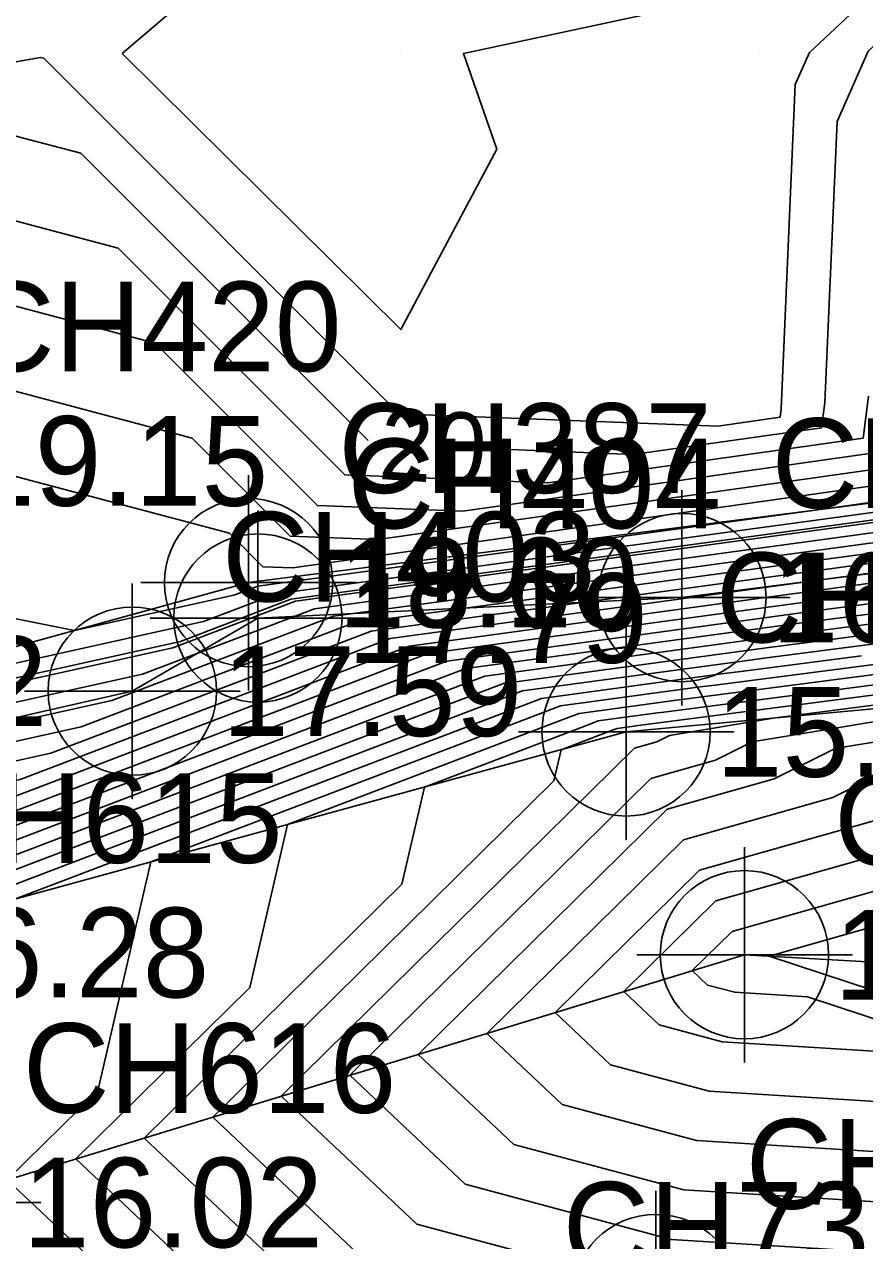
# Model space of a CAD drawing. Extents: x 2531902 to 2533249, y 715219 to 716099.
# Drawn here: x 2532819.51 to 2532842.92, y 715636.9 to 715670.81 of the extents above; entities that cross this region are included whole.
import ezdxf

# ---------------------------------------------------------------- set-up
doc = ezdxf.new("R2010")
doc.units = 0
for name, color, linetype in [('DTM Contours Major', 7, 'Continuous'), ('DTM Contours Major Text', 7, 'Continuous'), ('DTM Contours Minor', 7, 'Continuous'), ('Exist DTM Breakline', 7, 'Continuous'), ('Exist DTM Breakline Cogo Elevation', 7, 'Continuous'), ('Exist DTM Breakline Cogo Number', 7, 'Continuous'), ('Exist DTM Breakline Cogo Point CELL', 7, 'Continuous'), ('Exist DTM Breakline Underwater', 7, 'Continuous'), ('Exist DTM Breakline Underwater Cogo Elevation', 7, 'Continuous'), ('Exist DTM Breakline Underwater Cogo Number', 7, 'Continuous'), ('Exist DTM Breakline Underwater Cogo Point CELL', 7, 'Continuous'), ('Exist DTM Drainline', 7, 'Continuous'), ('Exist DTM Drainline Cogo Elevation', 7, 'Continuous'), ('Exist DTM Drainline Cogo Number', 7, 'Continuous'), ('Exist DTM Drainline Cogo Point CELL', 7, 'Continuous'), ('Exist DTM QL2 LIDAR Elevation Point', 7, 'Continuous'), ('Exist DTM Regular Point Cogo Elevation', 7, 'Continuous'), ('Exist DTM Regular Point Cogo Number', 7, 'Continuous'), ('Exist DTM Spot Elevation Cogo Number', 7, 'Continuous'), ('Exist Hydro Stream or Body of Water', 7, 'Continuous'), ('Scratch_Level_2', 7, 'Continuous')]:
    doc.layers.add(name, color=color, linetype=linetype)

msp = doc.modelspace()

# ---------------------------------------------------------------- linework, layer by layer
at = {"layer": 'DTM Contours Major'}
for points in [[(2532833.041, 715658.953), (2532836.467, 715658.82), (2532841.725, 715659.565), (2532841.817, 715660.266), (2532842.154, 715668.099), (2532843.02, 715670.063), (2532851.032, 715677.56), (2532857.094, 715681.734), (2532861.988, 715687.097), (2532863.701, 715689.359), (2532868.079, 715692.676), (2532874.442, 715703.544), (2532869.274, 715692.097), (2532867.616, 715688.507), (2532865.522, 715683.895), (2532864.57, 715681.832), (2532859.473, 715672.999)], [(2532787.963, 715647.113), (2532788.11, 715647.155), (2532790.468, 715647.623), (2532805.524, 715651.812), (2532807.289, 715651.681), (2532812.395, 715655.613), (2532820.905, 715653.907), (2532825.351, 715654.892), (2532826.014, 715655.145), (2532830.295, 715655.728), (2532841.623, 715657.272), (2532847.51, 715658.105), (2532847.908, 715661.158), (2532847.985, 715662.951), (2532851.196, 715670.232), (2532853.299, 715672.201), (2532858.259, 715675.616), (2532855.007, 715669.369), (2532850.728, 715661.954), (2532851.349, 715661.97)], [(2532742.632, 715654.879), (2532744.549, 715654.106), (2532746.734, 715656.99), (2532751.645, 715657.927), (2532759.371, 715659.033), (2532766.385, 715658.274), (2532769.514, 715656.994), (2532772.06, 715658.012), (2532779.096, 715657.172), (2532786.334, 715657.813), (2532789.538, 715657.253), (2532797.31, 715657.175), (2532801.18, 715658.251), (2532809.235, 715657.654), (2532811.722, 715659.569), (2532811.717, 715666.416), (2532819.095, 715667.743), (2532821.087, 715667.214), (2532829.089, 715659.21)], [(2532789.628, 715644.057), (2532793.839, 715645.27), (2532805.68, 715647.62), (2532808.608, 715648.444), (2532808.828, 715648.506), (2532821.098, 715651.224), (2532826.139, 715653.145), (2532828.649, 715654.101), (2532844.867, 715656.311), (2532846.614, 715656.538), (2532851.45, 715657.166), (2532860.686, 715660.385), (2532865.301, 715655.109), (2532866.396, 715654.713), (2532867.485, 715654.419), (2532869.624, 715653.149), (2532880.592, 715648.052), (2532883.273, 715646.806)], [(2532786.783, 715639.599), (2532788.186, 715640.107), (2532799.568, 715643.384), (2532804.204, 715644.304), (2532811.635, 715646.396), (2532811.727, 715646.422), (2532816.845, 715647.556), (2532829.641, 715652.432), (2532831.284, 715653.058), (2532841.899, 715654.505), (2532843.043, 715654.653), (2532855.32, 715656.247), (2532862.023, 715658.583), (2532865.372, 715654.754), (2532866.166, 715654.467), (2532866.956, 715654.253), (2532868.509, 715653.332), (2532876.468, 715649.633), (2532880.776, 715647.631)], [(2532855.566, 715634.305), (2532855.158, 715634.439), (2532837.18, 715635.559), (2532830.448, 715637.364), (2532826.67, 715640.927), (2532836.514, 715650.634), (2532837.135, 715650.81), (2532837.488, 715650.986), (2532840.375, 715651.464), (2532863.059, 715654.408), (2532864.695, 715654.979), (2532865.513, 715654.044), (2532865.707, 715653.974), (2532865.9, 715653.922), (2532866.279, 715653.697), (2532868.222, 715652.794), (2532871.592, 715651.227), (2532884.768, 715642.07), (2532887.226, 715640.345)], [(2532842.838, 715653.205), (2532839.472, 715652.768), (2532838.932, 715652.698), (2532833.919, 715652.015), (2532833.143, 715651.719), (2532819.223, 715646.415), (2532817.319, 715638.198), (2532817.128, 715638.01), (2532821.44, 715633.942)], [(2532856.997, 715637.752), (2532843.634, 715642.154), (2532838.95, 715642.446), (2532837.196, 715642.916), (2532836.212, 715643.844), (2532838.777, 715646.373), (2532845.302, 715648.224), (2532849.017, 715650.08), (2532864.862, 715652.703), (2532871.849, 715648.562), (2532884.074, 715640.066), (2532885.362, 715639.162), (2532893.985, 715631.35), (2532888.331, 715628.819), (2532883.327, 715629.556)]]:
    msp.add_lwpolyline(points, dxfattribs=at)
at = {"layer": 'DTM Contours Minor'}
for points in [[(2532800.412, 715670.412), (2532810, 715676.04), (2532816.6, 715680), (2532819.778, 715680.69), (2532820.314, 715680.122), (2532826.429, 715673.571), (2532822.24, 715670), (2532830, 715662.302), (2532832.673, 715667.327), (2532831.747, 715670), (2532838.481, 715671.44), (2532840, 715678.047), (2532841.386, 715680), (2532840, 715685.649), (2532836.476, 715683.524), (2532829.821, 715689.598), (2532829.107, 715690.165), (2532819.694, 715699.442), (2532810.011, 715699.987), (2532809.981, 715699.986), (2532809.699, 715700), (2532808.721, 715701.279), (2532801.023, 715710)], [(2532800.311, 715659.539), (2532809.625, 715658.849), (2532810.845, 715659.788), (2532810.839, 715668.249), (2532819.955, 715669.889), (2532820.053, 715669.863), (2532829.959, 715659.954), (2532838.836, 715659.611), (2532840.568, 715659.857), (2532840.598, 715660.088), (2532840.988, 715669.128), (2532841.385, 715670.029), (2532850.579, 715678.632)], [(2532795.329, 715655.094), (2532802.048, 715656.963), (2532808.846, 715656.459), (2532812.598, 715659.349), (2532812.594, 715664.583), (2532818.234, 715665.597), (2532822.121, 715664.566), (2532828.438, 715658.248), (2532834.098, 715658.029), (2532842.882, 715659.273), (2532843.035, 715660.444)], [(2532793.348, 715653.013), (2532802.917, 715655.675), (2532808.457, 715655.265), (2532813.475, 715659.13), (2532813.472, 715662.75), (2532817.373, 715663.451), (2532823.155, 715661.917), (2532827.677, 715657.394), (2532831.728, 715657.238), (2532844.039, 715658.981)], [(2532791.367, 715650.933), (2532803.786, 715654.387), (2532808.067, 715654.07), (2532814.352, 715658.91), (2532814.35, 715660.916), (2532816.512, 715661.305), (2532824.189, 715659.268), (2532826.916, 715656.541), (2532829.359, 715656.447), (2532845.196, 715658.689)], [(2532789.386, 715648.852), (2532804.655, 715653.1), (2532807.678, 715652.875), (2532815.229, 715658.69), (2532815.228, 715659.083), (2532815.652, 715659.16), (2532825.223, 715656.62), (2532826.155, 715655.688), (2532826.99, 715655.656), (2532846.353, 715658.397)], [(2532789.256, 715646.778), (2532802.068, 715649.321), (2532806.392, 715650.524), (2532806.899, 715650.486), (2532808.366, 715651.616), (2532810.81, 715651.126), (2532824.5, 715654.158), (2532826.541, 715654.936), (2532839.724, 715656.732), (2532847.24, 715657.757)], [(2532900.102, 715635.723), (2532888.893, 715641.875), (2532885.96, 715644.721), (2532885.74, 715644.876), (2532884.67, 715645.619), (2532873.994, 715650.581), (2532867.84, 715653.441), (2532866.639, 715654.154), (2532866.028, 715654.319), (2532865.414, 715654.541), (2532862.824, 715657.502), (2532857.642, 715655.695), (2532840.901, 715653.522), (2532840.119, 715653.421), (2532832.865, 715652.432), (2532831.742, 715652.004), (2532814.293, 715645.355), (2532813.467, 715645.172), (2532813.452, 715645.167), (2532803.318, 715642.315), (2532803.006, 715642.253), (2532802.238, 715642.032), (2532782.087, 715634.737)], [(2532790.402, 715646.401), (2532806.566, 715649.609), (2532806.791, 715649.672), (2532807.089, 715649.756), (2532823.65, 715653.425), (2532824.037, 715653.573), (2532827.068, 715654.727), (2532846.647, 715657.395)], [(2532791.548, 715646.024), (2532806.271, 715648.946), (2532807.397, 715649.263), (2532807.668, 715649.339), (2532822.799, 715652.691), (2532824.738, 715653.43), (2532827.595, 715654.519), (2532846.054, 715657.034)], [(2532901.681, 715634.486), (2532888.729, 715641.594), (2532886.177, 715644.071), (2532885.601, 715644.475), (2532882.802, 715646.42), (2532873.17, 715650.897), (2532867.617, 715653.478), (2532866.534, 715654.121), (2532865.982, 715654.269), (2532865.428, 715654.47), (2532863.092, 715657.141), (2532858.416, 715655.511), (2532840.186, 715653.145), (2532839.525, 715653.059), (2532833.392, 715652.224), (2532832.442, 715651.862), (2532815.412, 715645.372), (2532814.8, 715642.735), (2532809.568, 715640.234), (2532811.222, 715636.857)], [(2532792.694, 715645.647), (2532805.976, 715648.283), (2532808.002, 715648.853), (2532808.248, 715648.922), (2532821.948, 715651.958), (2532825.438, 715653.287), (2532828.122, 715654.31), (2532845.46, 715656.673)], [(2532904.838, 715632.011), (2532888.401, 715641.032), (2532886.611, 715642.77), (2532885.323, 715643.673), (2532879.065, 715648.023), (2532871.52, 715651.529), (2532867.171, 715653.551), (2532866.322, 715654.054), (2532865.89, 715654.171), (2532865.456, 715654.328), (2532863.626, 715656.42), (2532859.964, 715655.144), (2532838.758, 715652.391), (2532838.339, 715652.337), (2532834.446, 715651.806), (2532833.843, 715651.577), (2532823.034, 715647.458), (2532821.555, 715641.078), (2532819.036, 715638.593), (2532825.049, 715632.922)], [(2532800.714, 715643.007), (2532803.909, 715643.641), (2532812.241, 715645.987), (2532812.307, 715646.005), (2532815.994, 715646.822), (2532830.341, 715652.289), (2532831.811, 715652.849), (2532841.306, 715654.143), (2532842.329, 715654.276), (2532856.094, 715656.063)], [(2532906.417, 715630.774), (2532888.237, 715640.751), (2532886.828, 715642.119), (2532885.185, 715643.273), (2532877.197, 715648.824), (2532870.696, 715651.846), (2532866.948, 715653.587), (2532866.217, 715654.021), (2532865.845, 715654.122), (2532865.471, 715654.257), (2532863.894, 715656.06), (2532860.737, 715654.96), (2532838.044, 715652.014), (2532837.745, 715651.975), (2532834.973, 715651.598), (2532834.543, 715651.434), (2532826.846, 715648.501), (2532825.792, 715643.957), (2532820.944, 715639.177), (2532826.399, 715634.032)], [(2532794.985, 715644.893), (2532805.385, 715646.956), (2532809.213, 715648.034), (2532809.408, 715648.089), (2532820.247, 715650.49), (2532826.839, 715653.002), (2532829.176, 715653.893), (2532844.273, 715655.95)], [(2532797.554, 715641.39), (2532801.86, 715642.63), (2532803.614, 715642.978), (2532812.846, 715645.577), (2532812.887, 715645.588), (2532815.143, 715646.088), (2532831.041, 715652.147), (2532832.338, 715652.641), (2532840.712, 715653.782), (2532841.615, 715653.899), (2532856.868, 715655.879)], [(2532902.833, 715632.37), (2532888.074, 715640.47), (2532887.045, 715641.468), (2532885.046, 715642.872), (2532875.329, 715649.625), (2532869.871, 715652.162), (2532866.725, 715653.624), (2532866.111, 715653.988), (2532865.799, 715654.072), (2532865.485, 715654.186), (2532864.161, 715655.7), (2532861.511, 715654.776), (2532837.33, 715651.637), (2532837.152, 715651.614), (2532835.5, 715651.389), (2532835.244, 715651.292), (2532830.657, 715649.543), (2532830.029, 715646.836), (2532822.853, 715639.76), (2532827.748, 715635.143)], [(2532796.131, 715644.515), (2532805.09, 715646.293), (2532809.819, 715647.625), (2532809.988, 715647.672), (2532819.396, 715649.757), (2532827.539, 715652.86), (2532829.703, 715653.684), (2532843.68, 715655.589)], [(2532884.907, 715642.471), (2532873.46, 715650.426), (2532869.046, 715652.478), (2532866.502, 715653.66), (2532866.005, 715653.955), (2532865.753, 715654.023), (2532865.499, 715654.115), (2532864.428, 715655.339), (2532862.285, 715654.592), (2532836.615, 715651.26), (2532836.558, 715651.253), (2532836.027, 715651.18), (2532835.944, 715651.149), (2532834.468, 715650.586), (2532834.266, 715649.715), (2532824.761, 715640.344), (2532829.098, 715636.253)], [(2532797.277, 715644.138), (2532804.795, 715645.63), (2532810.424, 715647.215), (2532810.568, 715647.255), (2532818.546, 715649.023), (2532828.24, 715652.717), (2532830.23, 715653.475), (2532843.086, 715655.227)], [(2532798.422, 715643.761), (2532804.499, 715644.967), (2532811.03, 715646.806), (2532811.147, 715646.839), (2532817.695, 715648.289), (2532828.94, 715652.575), (2532830.757, 715653.267), (2532842.493, 715654.866), (2532843.757, 715655.03)], [(2532852.853, 715635.982), (2532837.534, 715636.936), (2532831.797, 715638.474), (2532828.578, 715641.511), (2532836.967, 715649.781), (2532838.768, 715650.293), (2532839.794, 715650.805), (2532848.173, 715652.192), (2532863.833, 715654.225), (2532864.963, 715654.618), (2532865.527, 715653.973), (2532865.661, 715653.925), (2532865.794, 715653.889), (2532866.056, 715653.733), (2532867.397, 715653.11), (2532869.724, 715652.029), (2532884.629, 715641.669), (2532887.473, 715639.673), (2532893.82, 715633.924)], [(2532856.138, 715635.684), (2532850.548, 715637.525), (2532837.888, 715638.314), (2532833.147, 715639.585), (2532830.487, 715642.094), (2532837.419, 715648.929), (2532840.402, 715649.776), (2532842.1, 715650.624), (2532855.971, 715652.92), (2532864.607, 715654.041), (2532865.23, 715654.258), (2532865.541, 715653.902), (2532865.615, 715653.875), (2532865.688, 715653.855), (2532865.833, 715653.77), (2532866.572, 715653.426), (2532867.856, 715652.83), (2532884.49, 715641.268), (2532886.945, 715639.546), (2532903.381, 715624.656), (2532902.622, 715624.317), (2532878.406, 715627.882), (2532862.803, 715633.42), (2532856.138, 715635.684)], [(2532856.424, 715636.373), (2532848.243, 715639.068), (2532838.242, 715639.691), (2532834.497, 715640.695), (2532832.395, 715642.678), (2532837.872, 715648.077), (2532842.035, 715649.258), (2532844.406, 715650.442), (2532863.769, 715653.648), (2532865.381, 715653.857), (2532865.497, 715653.897), (2532865.555, 715653.831), (2532865.569, 715653.826), (2532865.583, 715653.822), (2532865.61, 715653.806), (2532865.748, 715653.742), (2532865.987, 715653.631), (2532884.352, 715640.868), (2532886.417, 715639.418), (2532900.249, 715626.888), (2532897.858, 715625.818), (2532878.592, 715628.654), (2532866.178, 715633.06), (2532856.424, 715636.373)], [(2532856.71, 715637.063), (2532845.938, 715640.611), (2532838.596, 715641.069), (2532835.846, 715641.806), (2532834.303, 715643.261), (2532838.324, 715647.225), (2532843.668, 715648.741), (2532846.711, 715650.261), (2532865.255, 715653.331), (2532868.296, 715651.529), (2532884.213, 715640.467), (2532885.89, 715639.29), (2532897.117, 715629.119), (2532893.094, 715627.318), (2532878.778, 715629.426), (2532869.553, 715632.7), (2532856.71, 715637.063)], [(2532857.283, 715638.441), (2532841.329, 715643.697), (2532839.304, 715643.823), (2532838.546, 715644.026), (2532838.12, 715644.428), (2532839.229, 715645.521), (2532846.935, 715647.707), (2532851.323, 715649.899), (2532864.469, 715652.075), (2532875.402, 715645.596), (2532883.935, 715639.665), (2532884.834, 715639.034), (2532890.854, 715633.581), (2532883.567, 715630.32), (2532879.149, 715630.97), (2532876.303, 715631.981), (2532857.283, 715638.441)], [(2532879.001, 715631.851), (2532879.641, 715632.196), (2532887.722, 715635.812), (2532884.307, 715638.906), (2532883.796, 715639.264), (2532878.955, 715642.629), (2532864.076, 715651.447), (2532853.629, 715649.717), (2532848.568, 715647.19), (2532840.26, 715644.833), (2532857.569, 715639.131), (2532879.001, 715631.851)]]:
    msp.add_lwpolyline(points, dxfattribs=at)
at = {"layer": 'Exist DTM Breakline'}
msp.add_lwpolyline([(2532863.072, 715660.678), (2532859.426, 715662.085), (2532849.717, 715661.422), (2532847.724, 715658.051), (2532825.76, 715655.245), (2532806.743, 715650.005), (2532787.852, 715647.24), (2532777.892, 715646.595), (2532766.74, 715639.821), (2532753.665, 715642.294), (2532729.328, 715651.531), (2532716.286, 715652.801)], dxfattribs=at)
at = {"layer": 'Exist DTM Breakline Cogo Point CELL'}
for points in [[(2532825.76, 715658.245), (2532825.76, 715652.245), (2532825.76, 715655.245), (2532828.76, 715655.245), (2532822.76, 715655.245)], [(2532825.76, 715658.245), (2532825.76, 715652.245), (2532825.76, 715655.245), (2532828.76, 715655.245), (2532822.76, 715655.245)], [(2532837.833, 715657.827), (2532837.833, 715651.827), (2532837.833, 715654.827), (2532840.833, 715654.827), (2532834.833, 715654.827)], [(2532826.019, 715657.258), (2532826.019, 715651.258), (2532826.019, 715654.258), (2532829.019, 715654.258), (2532823.019, 715654.258)], [(2532822.52, 715655.218), (2532822.52, 715649.218), (2532822.52, 715652.218), (2532825.52, 715652.218), (2532819.52, 715652.218)]]:
    msp.add_lwpolyline(points, dxfattribs=at)
for centre in [(2532825.76, 715655.245), (2532825.76, 715655.245), (2532837.833, 715654.827), (2532826.019, 715654.258), (2532822.52, 715652.218)]:
    msp.add_circle(centre, 2.344, dxfattribs=at)
at = {"layer": 'Exist DTM Breakline Underwater'}
msp.add_lwpolyline([(2532646.748, 715755.182), (2532668.676, 715717.147), (2532677.241, 715702.567), (2532689.842, 715666.582), (2532701.723, 715652.924), (2532713.134, 715647.155), (2532737.59, 715643.253), (2532756.176, 715636.457), (2532783.406, 715639.452), (2532803.254, 715642.171), (2532813.801, 715644.931), (2532836.277, 715651.081), (2532865.559, 715653.815), (2532885.826, 715645.124), (2532889.946, 715643.683), (2532906.865, 715630.423), (2532927.34, 715618.228), (2532957.965, 715607.729), (2532978.566, 715598.571), (2533001.091, 715586.568), (2533028.19, 715572.821)], dxfattribs=at)
at = {"layer": 'Exist DTM Breakline Underwater Cogo Point CELL'}
for points in [[(2532836.277, 715654.081), (2532836.277, 715648.081), (2532836.277, 715651.081), (2532839.277, 715651.081), (2532833.277, 715651.081)], [(2532837.11, 715638.289), (2532837.11, 715632.289), (2532837.11, 715635.289), (2532840.11, 715635.289), (2532834.11, 715635.289)]]:
    msp.add_lwpolyline(points, dxfattribs=at)
for centre in [(2532836.277, 715651.081), (2532837.11, 715635.289)]:
    msp.add_circle(centre, 2.344, dxfattribs=at)
at = {"layer": 'Exist DTM Drainline'}
msp.add_lwpolyline([(2532712.089, 715642.317), (2532734.218, 715637.287), (2532753.576, 715632.211), (2532781.659, 715633.208), (2532801.91, 715635.068), (2532816.971, 715637.962), (2532839.573, 715644.872), (2532859.48, 715643.736), (2532879.315, 715631.66), (2532904.837, 715623.619), (2532925.407, 715612.713), (2532951.291, 715602.124), (2532975.159, 715591.05), (2532999.274, 715579.213), (2533023.429, 715565.909)], dxfattribs=at)
at = {"layer": 'Exist DTM Drainline Cogo Point CELL'}
for points in [[(2532839.573, 715647.872), (2532839.573, 715641.872), (2532839.573, 715644.872), (2532842.573, 715644.872), (2532836.573, 715644.872)], [(2532816.971, 715640.962), (2532816.971, 715634.962), (2532816.971, 715637.962), (2532819.971, 715637.962), (2532813.971, 715637.962)]]:
    msp.add_lwpolyline(points, dxfattribs=at)
msp.add_circle((2532839.573, 715644.872), 2.344, dxfattribs=at)
at = {"layer": 'Exist DTM QL2 LIDAR Elevation Point'}
for p, q in [((2532820, 715670), (2532820, 715670)), ((2532830, 715670), (2532830, 715670)), ((2532840, 715670), (2532840, 715670)), ((2532830, 715660), (2532830, 715660)), ((2532840, 715660), (2532840, 715660))]:
    msp.add_line(p, q, dxfattribs=at)
at = {"layer": 'Exist Hydro Stream or Body of Water'}
msp.add_lwpolyline([(2532790.115, 715646.495), (2532806.64, 715649.775), (2532806.944, 715649.86), (2532823.862, 715653.608), (2532826.936, 715654.78), (2532846.795, 715657.486), (2532848.935, 715657.763), (2532859.818, 715661.557), (2532865.255, 715655.34), (2532866.545, 715654.873), (2532867.828, 715654.527), (2532870.349, 715653.031), (2532883.272, 715647.025), (2532884.83, 715646.372), (2532885.882, 715645.762), (2532886.539, 715645.426), (2532889.693, 715644.068), (2532889.952, 715644.137), (2532891.522, 715643.982), (2532891.782, 715643.826), (2532896.496, 715640.921), (2532907.078, 715634.646)], dxfattribs=at)
at = {"layer": 'Scratch_Level_2'}
msp.add_lwpolyline([(2532714.118, 715649.677), (2532729.178, 715648.995), (2532753.386, 715638.683), (2532767.656, 715638.089), (2532777.579, 715641.803), (2532788.373, 715643.181), (2532801.718, 715645.997), (2532807.244, 715648.747), (2532822.52, 715652.218), (2532826.019, 715654.258), (2532837.833, 715654.827), (2532847.619, 715656.074), (2532850.366, 715659.741), (2532854.722, 715660.175), (2532860.554, 715659.882), (2532861.668, 715659.678), (2532862.953, 715658.263)], dxfattribs=at)

# ---------------------------------------------------------------- texts
at = {"layer": 'DTM Contours Major Text'}
msp.add_text('20', height=2, rotation=356.2659, dxfattribs=at).set_placement((2532829.351, 715658.138))
at = {"layer": 'Exist DTM Breakline Cogo Elevation'}
for s, p in [('18.60', (2532828.26, 715653.995)), ('19.10', (2532828.26, 715653.995)), ('16.83', (2532840.333, 715653.577)), ('17.79', (2532828.519, 715653.008)), ('17.59', (2532825.02, 715650.968))]:
    msp.add_text(s, height=2.5, dxfattribs=at).set_placement(p)
at = {"layer": 'Exist DTM Breakline Cogo Number'}
for s, p in [('CH387', (2532828.26, 715657.745)), ('CH387', (2532828.26, 715657.745)), ('CH405', (2532840.333, 715657.327)), ('CH404', (2532828.519, 715656.758)), ('CH403', (2532825.02, 715654.718)), ('CH402', (2532809.744, 715651.247))]:
    msp.add_text(s, height=2.5, dxfattribs=at).set_placement(p)
at = {"layer": 'Exist DTM Breakline Underwater Cogo Elevation'}
for s, p in [('15.11', (2532838.777, 715649.831)), ('16.28', (2532816.301, 715643.681))]:
    msp.add_text(s, height=2.5, dxfattribs=at).set_placement(p)
at = {"layer": 'Exist DTM Breakline Underwater Cogo Number'}
for s, p in [('CH618', (2532838.777, 715653.581)), ('CH615', (2532816.301, 715647.431)), ('CH620', (2532839.61, 715637.789)), ('CH733', (2532834.511, 715636.036))]:
    msp.add_text(s, height=2.5, dxfattribs=at).set_placement(p)
at = {"layer": 'Exist DTM Drainline Cogo Elevation'}
for s, p in [('13.65', (2532842.073, 715643.622)), ('16.02', (2532819.471, 715636.712))]:
    msp.add_text(s, height=2.5, dxfattribs=at).set_placement(p)
at = {"layer": 'Exist DTM Drainline Cogo Number'}
for s, p in [('CH619', (2532842.073, 715647.372)), ('CH616', (2532819.471, 715640.462))]:
    msp.add_text(s, height=2.5, dxfattribs=at).set_placement(p)
at = {"layer": 'Exist DTM Regular Point Cogo Elevation'}
msp.add_text('19.15', height=2.5, dxfattribs=at).set_placement((2532817.942, 715657.387))
at = {"layer": 'Exist DTM Regular Point Cogo Number'}
msp.add_text('CH420', height=2.5, dxfattribs=at).set_placement((2532817.942, 715661.137))
at = {"layer": 'Exist DTM Spot Elevation Cogo Number'}
msp.add_text('CH733', height=2.5, dxfattribs=at).set_placement((2532834.511, 715636.036))

doc.saveas('drawing.dxf')
